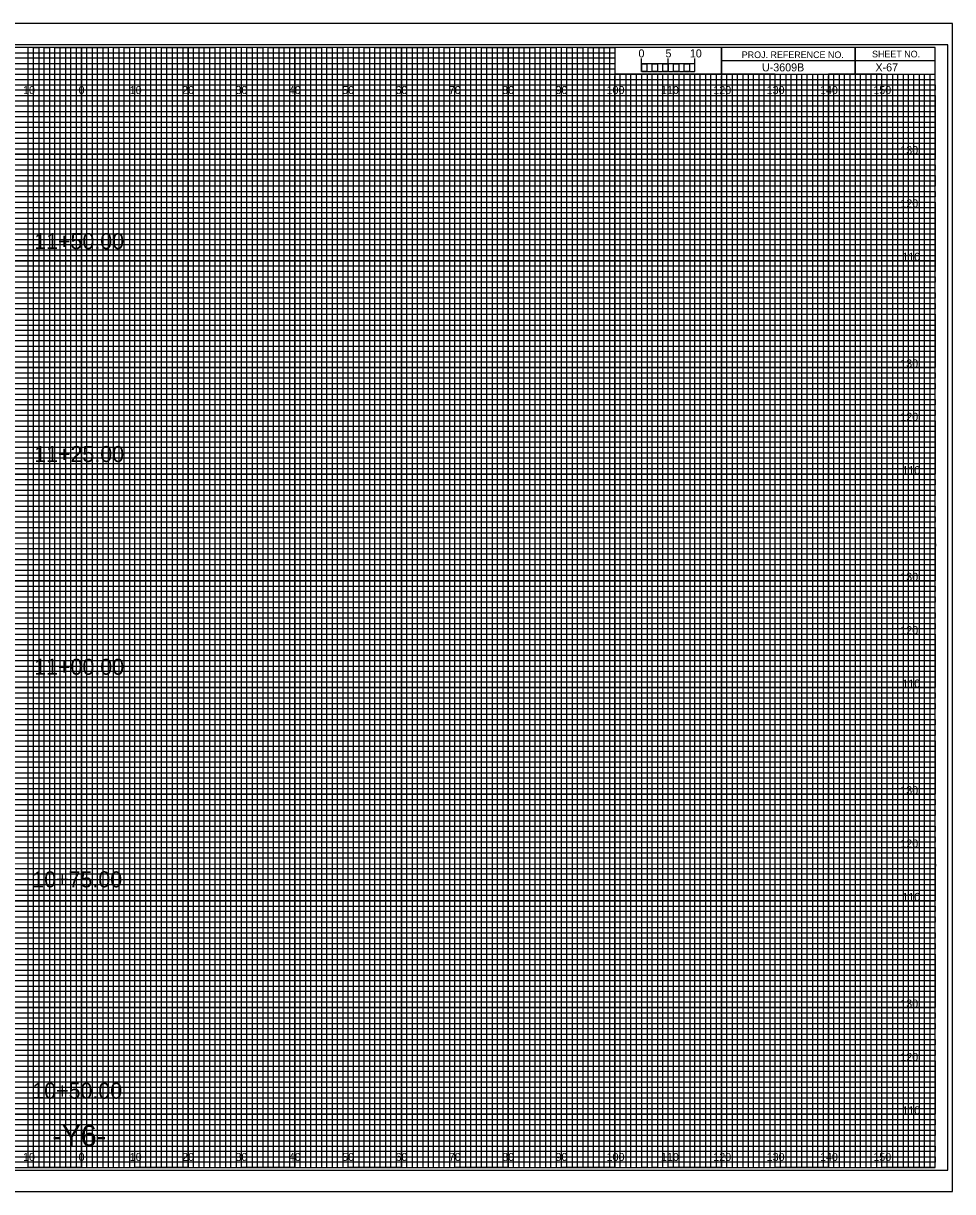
# Model space of a CAD drawing. Extents: x -13 to 323, y -5 to 434.
# Drawn here: x 149.1 to 323.3, y -4.5 to 214.5 of the extents above; entities that cross this region are included whole.
import ezdxf

# ---------------------------------------------------------------- set-up
doc = ezdxf.new("R2010")
doc.units = 0
for name, color, linetype in [('Exist CMT Pavement', 7, 'Continuous'), ('Exist Cross Section Cell', 7, 'Continuous'), ('Exist XS Center Line Elevation Label', 7, 'Continuous'), ('Exist XS Ground Line', 7, 'Continuous'), ('Prop CMT Concrete Structures', 7, 'Continuous'), ('Prop CMT Pvmt Course 1 CG', 7, 'Continuous'), ('Prop CMT Pvmt Course 1 Wedge', 7, 'Continuous'), ('Prop CMT Pvmt Course 2', 7, 'Continuous'), ('Prop CMT Pvmt Course 2 Wedge', 7, 'Continuous'), ('Prop CMT Pvmt Course 3', 7, 'Continuous'), ('Prop CMT Pvmt Course 3 Wedge', 7, 'Continuous'), ('Prop CMT Pvmt Surface', 7, 'Continuous'), ('Prop CMT Pvmt Wedge Surface 1', 7, 'Continuous'), ('Prop CMT Pvmt Wedge Surface 2', 7, 'Continuous'), ('Prop CMT Pvmt Wedge Surface 3', 7, 'Continuous'), ('Prop CMT Subgrade Earthwork', 7, 'Continuous'), ('Scratch_Level_0', 7, 'Continuous')]:
    doc.layers.add(name, color=color, linetype=linetype)

msp = doc.modelspace()

# ---------------------------------------------------------------- linework, layer by layer
at = {"layer": 'Exist XS Center Line Elevation Label'}
for points in [[(145, 0), (155, 0), (155, 210), (165, 210), (165, 0), (175, 0), (175, 210), (185, 210), (185, 0), (195, 0), (195, 210), (205, 210), (205, 0), (215, 0), (215, 210), (225, 210), (225, 0), (235, 0), (235, 210), (245, 210), (245, 0), (255, 0), (255, 210), (259.93, 210), (260, 210), (260, 205), (264.99, 205), (264.99, 0), (275, 0), (275, 205), (285, 205), (285, 0), (295, 0), (295, 205), (305, 205), (305, 0), (315, 0), (315, 205)], [(0, 205), (275, 205)], [(0, 185), (320, 185), (320, 195), (0, 195)], [(0, 165), (320, 165), (320, 175), (0, 175)], [(0, 145), (320, 145), (320, 155), (0, 155)], [(0, 125), (320, 125), (320, 135), (0, 135)], [(0, 105), (320, 105), (320, 115), (0, 115)], [(0, 85), (320, 85), (320, 95), (0, 95)], [(0, 65), (320, 65), (320, 75), (0, 75)], [(0, 45), (320, 45), (320, 55), (0, 55)], [(0, 25), (320, 25), (320, 35), (0, 35)], [(0, 5), (320, 5), (320, 15), (0, 15)]]:
    msp.add_lwpolyline(points, dxfattribs=at)
at = {"layer": 'Exist XS Ground Line'}
for p, q in [((150, 210), (140, 210)), ((150, 0), (150, 210)), ((170, 210), (160, 210)), ((160, 210), (160, 0)), ((170, 0), (170, 210)), ((190, 210), (180, 210)), ((180, 210), (180, 0)), ((190, 0), (190, 210)), ((210, 210), (200, 210)), ((200, 210), (200, 0)), ((210, 0), (210, 210)), ((230, 210), (220, 210)), ((220, 210), (220, 0)), ((230, 0), (230, 210)), ((250, 210), (240, 210)), ((240, 210), (240, 0)), ((250, 0), (250, 210)), ((260, 210), (260, 0)), ((270, 0), (270, 205)), ((290, 205), (280, 205)), ((280, 205), (280, 0)), ((290, 0), (290, 205)), ((310, 205), (300, 205)), ((300, 205), (300, 0)), ((310, 0), (310, 205)), ((160, 0), (150, 0)), ((180, 0), (170, 0)), ((200, 0), (190, 0)), ((220, 0), (210, 0)), ((240, 0), (230, 0)), ((260, 0), (250, 0)), ((280, 0), (270, 0)), ((300, 0), (290, 0)), ((320, 0), (310, 0)), ((320, 0), (320, 0))]:
    msp.add_line(p, q, dxfattribs=at)
for points in [[(0, 200), (320, 200), (320, 190), (0, 190)], [(0, 180), (320, 180), (320, 170), (0, 170)], [(0, 160), (320, 160), (320, 150), (0, 150)], [(0, 140), (320, 140), (320, 130), (0, 130)], [(0, 120), (320, 120), (320, 110), (0, 110)], [(0, 100), (320, 100), (320, 90), (0, 90)], [(0, 80), (320, 80), (320, 70), (0, 70)], [(0, 60), (320, 60), (320, 50), (0, 50)], [(0, 40), (320, 40), (320, 30), (0, 30)], [(0, 20), (320, 20), (320, 10), (0, 10)]]:
    msp.add_lwpolyline(points, dxfattribs=at)
at = {"layer": 'Prop CMT Concrete Structures'}
for p, q in [((323.3, 214.5), (-13.4, 214.5)), ((-13.4, -4.5), (323.3, -4.5))]:
    msp.add_line(p, q, dxfattribs=at)
at = {"layer": 'Prop CMT Pvmt Course 1 Wedge'}
msp.add_lwpolyline([(-13.4, -4.5), (323.3, -4.5), (323.3, 214.5), (-13.4, 214.5)], close=True, dxfattribs=at)
at = {"layer": 'Prop CMT Pvmt Course 2'}
for p, q in [((305, 210), (305, 205)), ((305, 205), (305, 210)), ((280, 207.5), (280, 205)), ((320, 207.49), (280, 207.49)), ((280, 205), (320, 205))]:
    msp.add_line(p, q, dxfattribs=at)
for points in [[(320, 210), (0, 210), (0, 0), (320, 0)], [(280, 210), (260, 210), (260, 205.03), (280, 205.03)], [(320, 210), (280, 210), (280, 205), (320, 205)]]:
    msp.add_lwpolyline(points, close=True, dxfattribs=at)
at = {"layer": 'Prop CMT Pvmt Course 2 Wedge'}
msp.add_lwpolyline([(-10.8, -0.5), (322.4, -0.5), (322.4, 210.5), (-10.8, 210.5)], close=True, dxfattribs=at)
at = {"layer": 'Prop CMT Pvmt Course 3'}
for p, q in [((267, 205), (266.01, 205)), ((266.01, 205), (266.01, 0)), ((267, 0), (267, 205)), ((269, 205), (268, 205)), ((268, 205), (268, 0)), ((269, 0), (269, 205)), ((266.01, 0), (265, 0)), ((268, 0), (267, 0))]:
    msp.add_line(p, q, dxfattribs=at)
for points in [[(150, 0), (151, 0), (151, 210), (152, 210), (152, 0)], [(152, 0), (153, 0), (153, 210), (154, 210), (154, 0)], [(155, 0), (156, 0), (156, 210), (157, 210), (157, 0)], [(157, 0), (158, 0), (158, 210), (159, 210), (159, 0)], [(160, 0), (161, 0), (161, 210), (162, 210), (162, 0)], [(162, 0), (163, 0), (163, 210), (164, 210), (164, 0)], [(165, 0), (166, 0), (166, 210), (167, 210), (167, 0)], [(167, 0), (168, 0), (168, 210), (169, 210), (169, 0)], [(170, 0), (171, 0), (171, 210), (172, 210), (172, 0)], [(172, 0), (173, 0), (173, 210), (174, 210), (174, 0)], [(175, 0), (176, 0), (176, 210), (177, 210), (177, 0)], [(177, 0), (178, 0), (178, 210), (179, 210), (179, 0)], [(180, 0), (181, 0), (181, 210), (182, 210), (182, 0)], [(182, 0), (183, 0), (183, 210), (184, 210), (184, 0)], [(185, 0), (186, 0), (186, 210), (187, 210), (187, 0)], [(187, 0), (188, 0), (188, 210), (189, 210), (189, 0)], [(190, 0), (191, 0), (191, 210), (192, 210), (192, 0)], [(192, 0), (193, 0), (193, 210), (194, 210), (194, 0)], [(195, 0), (196, 0), (196, 210), (197, 210), (197, 0)], [(197, 0), (198, 0), (198, 210), (199, 210), (199, 0)], [(200, 0), (201, 0), (201, 210), (202, 210), (202, 0)], [(202, 0), (203, 0), (203, 210), (204, 210), (204, 0)], [(205, 0), (206, 0), (206, 210), (207, 210), (207, 0)], [(207, 0), (208, 0), (208, 210), (209, 210), (209, 0)], [(210, 0), (211, 0), (211, 210), (212, 210), (212, 0)], [(212, 0), (213, 0), (213, 210), (214, 210), (214, 0)], [(215, 0), (216, 0), (216, 210), (217, 210), (217, 0)], [(217, 0), (218, 0), (218, 210), (219, 210), (219, 0)], [(220, 0), (221, 0), (221, 210), (222, 210), (222, 0)], [(222, 0), (223, 0), (223, 210), (224, 210), (224, 0)], [(225, 0), (226, 0), (226, 210), (227, 210), (227, 0)], [(227, 0), (228, 0), (228, 210), (229, 210), (229, 0)], [(230, 0), (231, 0), (231, 210), (232, 210), (232, 0)], [(232, 0), (233, 0), (233, 210), (234, 210), (234, 0)], [(235, 0), (236, 0), (236, 210), (237, 210), (237, 0)], [(237, 0), (238, 0), (238, 210), (239, 210), (239, 0)], [(240, 0), (241, 0), (241, 210), (242, 210), (242, 0)], [(242, 0), (243, 0), (243, 210), (244, 210), (244, 0)], [(245, 0), (246, 0), (246, 210), (247, 210), (247, 0)], [(247, 0), (248, 0), (248, 210), (249, 210), (249, 0)], [(250, 0), (251, 0), (251, 210), (252, 210), (252, 0)], [(252, 0), (253, 0), (253, 210), (254, 210), (254, 0)], [(255, 0), (256, 0), (256, 210), (257, 210), (257, 0)], [(257, 0), (258, 0), (258, 210), (259, 210), (259, 0)], [(260, 0), (261, 0), (261, 205), (262.02, 205), (262.02, 0)], [(262, 0), (263, 0), (263, 205), (263.99, 205), (263.99, 0)], [(270, 0), (270.98, 0), (270.98, 205), (272, 205), (272, 0)], [(272, 0), (273, 0), (273, 205), (274.05, 205), (274.05, 0)], [(275, 0), (276, 0), (276, 205), (277, 205), (277, 0)], [(277, 0), (278, 0), (278, 205), (279, 205), (279, 0)], [(280, 0), (281, 0), (281, 205), (282, 205), (282, 0)], [(282, 0), (283, 0), (283, 205), (284, 205), (284, 0)], [(285, 0), (286, 0), (286, 205), (287, 205), (287, 0)], [(287, 0), (288, 0), (288, 205), (289, 205), (289, 0)], [(290, 0), (291, 0), (291, 205), (292, 205), (292, 0)], [(292, 0), (293, 0), (293, 205), (294, 205), (294, 0)], [(295, 0), (296, 0), (296, 205), (297, 205), (297, 0)], [(297, 0), (298, 0), (298, 205), (299, 205), (299, 0)], [(300, 0), (301, 0), (301, 205), (302, 205), (302, 0)], [(302, 0), (303, 0), (303, 205), (304, 205), (304, 0)], [(305, 0), (306, 0), (306, 205), (307, 205), (307, 0)], [(307, 0), (308, 0), (308, 205), (309, 205), (309, 0)], [(310, 0), (311, 0), (311, 205), (312, 205), (312, 0)], [(312, 0), (313, 0), (313, 205), (314, 205), (314, 0)], [(315, 0), (316, 0), (316, 205), (317, 205), (317, 0)], [(317, 0), (318, 0), (318, 205), (319, 205), (319, 0)]]:
    msp.add_lwpolyline(points, dxfattribs=at)
at = {"layer": 'Prop CMT Pvmt Course 3 Wedge'}
for p, q in [((150, 0), (150, 210)), ((160, 0), (160, 210)), ((170, 0), (170, 210)), ((180, 0), (180, 210)), ((190, 0), (190, 210)), ((200, 0), (200, 210)), ((210, 0), (210, 210)), ((220, 0), (220, 210)), ((230, 0), (230, 210)), ((240, 0), (240, 210)), ((250, 0), (250, 210)), ((260, 0), (260, 204.69)), ((270, 0), (270, 204.69)), ((280, 0), (280, 204.69)), ((290, 0), (290, 204.69)), ((300, 0), (300, 204.69)), ((310, 0), (310, 204.69)), ((0, 200), (320, 200)), ((0, 190), (320, 190)), ((0, 180), (320, 180)), ((0, 170), (320, 170)), ((0, 160), (320, 160)), ((0, 150), (320, 150)), ((0, 140), (320, 140)), ((0, 130), (320, 130)), ((0, 120), (320, 120)), ((0, 110), (320, 110)), ((0, 100), (320, 100)), ((0, 90), (320, 90)), ((0, 80), (320, 80)), ((0, 70), (320, 70)), ((0, 60), (320, 60)), ((0, 50), (320, 50)), ((0, 40), (320, 40)), ((0, 30), (320, 30)), ((0, 20), (320, 20)), ((0, 10), (320, 10))]:
    msp.add_line(p, q, dxfattribs=at)
at = {"layer": 'Prop CMT Subgrade Earthwork'}
for p, q in [((265, 205.49), (265, 207.9)), ((265, 206.9), (265, 207.9)), ((270, 205.49), (270, 207.9)), ((275, 205.49), (275, 207.9)), ((275, 206.9), (275, 207.9))]:
    msp.add_line(p, q, dxfattribs=at)
for points in [[(275, 206.9), (265, 206.9), (265, 205.49), (275, 205.49)], [(265, 206.9), (266, 206.9), (266, 205.49), (265, 205.49)], [(267, 206.9), (268, 206.9), (268, 205.49), (267, 205.49)], [(269, 206.9), (270, 206.9), (270, 205.49), (269, 205.49)], [(271, 206.9), (272, 206.9), (272, 205.49), (271, 205.49)], [(273, 206.9), (274, 206.9), (274, 205.49), (273, 205.49)]]:
    msp.add_lwpolyline(points, close=True, dxfattribs=at)
at = {"layer": 'Scratch_Level_0'}
for p, q in [((0, 209), (260, 209)), ((260, 209), (260, 207.98)), ((260, 207.98), (0, 207.98)), ((0, 207), (260, 207)), ((260, 205.89), (0, 205.89)), ((260, 207), (260, 205.89)), ((0, 204), (320, 204))]:
    msp.add_line(p, q, dxfattribs=at)
for points in [[(0, 203), (270, 203), (320, 203), (320, 202), (0, 202)], [(0, 201), (320, 201), (320, 199), (0, 199)], [(0, 198), (320, 198), (320, 197), (0, 196.98)], [(0, 196), (320, 196), (320, 194), (0, 194)], [(0, 193), (320, 193), (320, 192), (0, 192)], [(0, 191), (320, 191), (320, 189), (0, 189)], [(0, 188), (320, 188), (320, 187), (0, 187)], [(0, 186), (320, 186), (320, 184), (0, 184)], [(0, 183), (320, 183), (320, 182), (0, 182)], [(0, 181), (320, 181), (320, 179), (0, 179)], [(0, 178), (320, 178), (320, 177), (0, 177)], [(0, 176), (320, 176), (320, 173.95), (320, 173), (320, 172), (0, 172)], [(0, 174), (320, 174), (320, 173), (0, 173)], [(0, 171), (320, 171), (320, 169), (0, 169.03)], [(0, 169.03), (320, 169), (320, 168), (0, 168)], [(0, 167), (320, 167), (320, 166), (0, 166)], [(0, 164), (320, 164), (320, 163), (0, 163)], [(0, 162), (320, 162), (320, 161), (0, 161)], [(-0.07, 158.89), (320, 158.89), (320, 157.88), (-0.07, 157.88)], [(0, 157), (320, 157), (320, 156), (0, 156)], [(0, 154), (320, 154), (320, 153), (0, 153)], [(0, 152), (320, 152), (320, 151), (0, 151)], [(0, 149), (320, 149), (320, 148), (0, 148)], [(0, 147), (320, 147), (320, 146), (0, 146)], [(0, 144), (320, 144), (320, 143), (0, 143)], [(0, 142), (320, 142), (320, 141), (0, 141)], [(0, 139), (320, 139), (319.99, 137.98), (0, 138)], [(0, 137), (320, 137), (320, 136), (0, 136)], [(0, 134), (320, 134), (320, 133), (0, 133)], [(0, 132), (320, 132), (320, 131), (0, 131)], [(0, 129), (320, 129), (320, 128), (0, 128)], [(0, 127), (320, 127), (320, 126), (0, 126)], [(0, 124), (320, 124), (320, 123), (0, 123)], [(0, 122), (320, 122), (320, 121), (0, 121)], [(0, 119), (320, 119), (320, 118), (0, 118)], [(0, 116.99), (320.07, 116.91), (320, 116), (0, 116)], [(0, 114), (320, 114), (320, 113), (0, 113)], [(0, 112), (320, 112), (320, 111), (0, 111)], [(0, 109), (320, 109), (320, 108), (0, 108)], [(0, 107), (320, 107), (320, 106), (0, 106)], [(0, 104), (320, 104), (320, 103), (0, 103)], [(0, 102), (320, 102), (320, 101), (0, 101)], [(0, 99), (320, 99), (320, 98), (0, 98)], [(0, 97), (320, 97), (320, 96), (0, 96)], [(0, 94), (320, 94), (320, 93), (0, 93)], [(0, 92), (320, 92), (320, 91), (0, 91)], [(0, 89), (320, 89), (320, 88), (0, 88)], [(0, 87), (320, 87), (320, 86), (0, 86)], [(0, 84), (320, 84), (320, 83), (0, 83)], [(0, 82), (320, 82), (320, 81), (0, 81)], [(0, 79), (320, 79), (319.99, 77.98), (0, 78)], [(0, 77), (320, 77), (320, 76), (0, 76)], [(0, 74), (320, 74), (320, 73), (0, 73)], [(0, 72), (320, 72), (320, 71), (0, 71)], [(0, 69), (320, 69), (320, 68), (0, 68)], [(0, 67), (320, 67), (320, 66), (0, 66)], [(0, 64), (320, 64), (320, 63), (0, 63)], [(0, 62), (320, 62), (320, 61), (0, 61)], [(0, 59), (320, 59), (320, 58), (0, 58)], [(0, 56.99), (320.07, 56.91), (320, 56), (0, 56)], [(0, 54), (320, 54), (320, 53), (0, 53)], [(0, 52), (320, 52), (320, 51), (0, 51)], [(0, 49), (320, 49), (320, 48), (0, 48)], [(0, 47), (320, 47), (320, 46), (0, 46)], [(0, 44), (320, 44), (320, 43), (0, 43)], [(0, 42), (320, 42), (320, 41), (0, 41)], [(0, 39), (320, 39), (320, 38), (0, 38)], [(0, 37), (320, 37), (320, 36), (0, 36)], [(0, 34), (320, 34), (320, 33), (0, 33)], [(0, 32), (320, 32), (320, 31), (0, 31)], [(0, 29), (320, 29), (320, 28), (0, 28)], [(0, 27), (320, 27), (320, 26), (0, 26)], [(0, 24), (320, 24), (320, 23), (0, 23)], [(0, 22), (320, 22), (320, 21), (0, 21)], [(0, 19), (320, 19), (320, 18), (0, 18)], [(0, 17), (320, 17), (320, 16), (0, 16)], [(0, 14), (320, 14), (320, 13), (0, 13)], [(0, 12), (320, 12), (320, 11), (0, 11)], [(0, 9), (320, 9), (320, 8), (0, 8)], [(0, 7), (320, 7), (320, 6), (0, 6)], [(0, 4), (320, 4), (320, 3), (0, 3)], [(0, 2), (320, 2), (320, 1), (0, 1)]]:
    msp.add_lwpolyline(points, dxfattribs=at)

# ---------------------------------------------------------------- texts
at = {"layer": 'Exist CMT Pavement'}
for s, p in [('130', (313.49, 190)), ('120', (313.5, 180)), ('110', (313.88, 170)), ('130', (313.49, 150)), ('120', (313.5, 140)), ('110', (313.88, 130)), ('130', (313.49, 110)), ('120', (313.5, 100)), ('110', (313.88, 90)), ('130', (313.49, 70)), ('120', (313.5, 60)), ('110', (313.88, 50)), ('130', (313.49, 30)), ('120', (313.5, 20)), ('110', (313.88, 10))]:
    msp.add_text(s, height=1.5, dxfattribs=at).set_placement(p)
at = {"layer": 'Exist Cross Section Cell'}
for s, p in [('10', (149.04, 201.25)), ('0', (159.45, 201.25)), ('0', (159.45, 201.25)), ('10', (169.04, 201.25)), ('20', (178.86, 201.25)), ('30', (188.86, 201.25)), ('40', (198.86, 201.25)), ('50', (208.86, 201.25)), ('60', (218.86, 201.25)), ('70', (228.86, 201.25)), ('80', (238.86, 201.25)), ('90', (248.86, 201.25)), ('100', (258.44, 201.25)), ('110', (268.62, 201.25)), ('120', (278.44, 201.25)), ('130', (288.44, 201.25)), ('140', (298.44, 201.25)), ('150', (308.44, 201.25)), ('10', (149.04, 1.25)), ('0', (159.45, 1.25)), ('0', (159.45, 1.25)), ('10', (169.04, 1.25)), ('20', (178.86, 1.25)), ('30', (188.86, 1.25)), ('40', (198.86, 1.25)), ('50', (208.86, 1.25)), ('60', (218.86, 1.25)), ('70', (228.86, 1.25)), ('80', (238.86, 1.25)), ('90', (248.86, 1.25)), ('100', (258.44, 1.25)), ('110', (268.62, 1.25)), ('120', (278.44, 1.25)), ('130', (288.44, 1.25)), ('140', (298.44, 1.25)), ('150', (308.44, 1.25))]:
    msp.add_text(s, height=1.5, dxfattribs=at).set_placement(p)
at = {"layer": 'Prop CMT Pvmt Course 1 CG'}
msp.add_text('X-67', height=1.5, dxfattribs=at).set_placement((308.83, 205.5))
at = {"layer": 'Prop CMT Pvmt Course 2'}
for s, p in [('PROJ. REFERENCE NO.', (283.77, 207.99)), ('SHEET NO.', (308.19, 208.12))]:
    msp.add_text(s, height=1.25, dxfattribs=at).set_placement(p)
at = {"layer": 'Prop CMT Pvmt Surface'}
for s, p in [('11+50.00', (151.13, 172.18)), ('11+25.00', (151.13, 132.27)), ('11+00.00', (151.13, 92.39)), ('10+75.00', (150.77, 52.54)), ('10+50.00', (150.77, 12.92))]:
    msp.add_text(s, height=3, dxfattribs=at).set_placement(p)
at = {"layer": 'Prop CMT Pvmt Wedge Surface 1'}
msp.add_text('U-3609B', height=1.5, dxfattribs=at).set_placement((287.56, 205.5))
at = {"layer": 'Prop CMT Pvmt Wedge Surface 2'}
msp.add_text('-Y6-', height=4, dxfattribs=at).set_placement((154.52, 4))
at = {"layer": 'Prop CMT Pvmt Wedge Surface 3'}
for s, p in [('5', (269.47, 208.12)), ('10', (274.04, 208.12))]:
    msp.add_text(s, height=1.5, dxfattribs=at).set_placement(p)
at = {"layer": 'Prop CMT Subgrade Earthwork'}
msp.add_text('0', height=1.5, dxfattribs=at).set_placement((264.41, 208.12))

doc.saveas('drawing.dxf')
